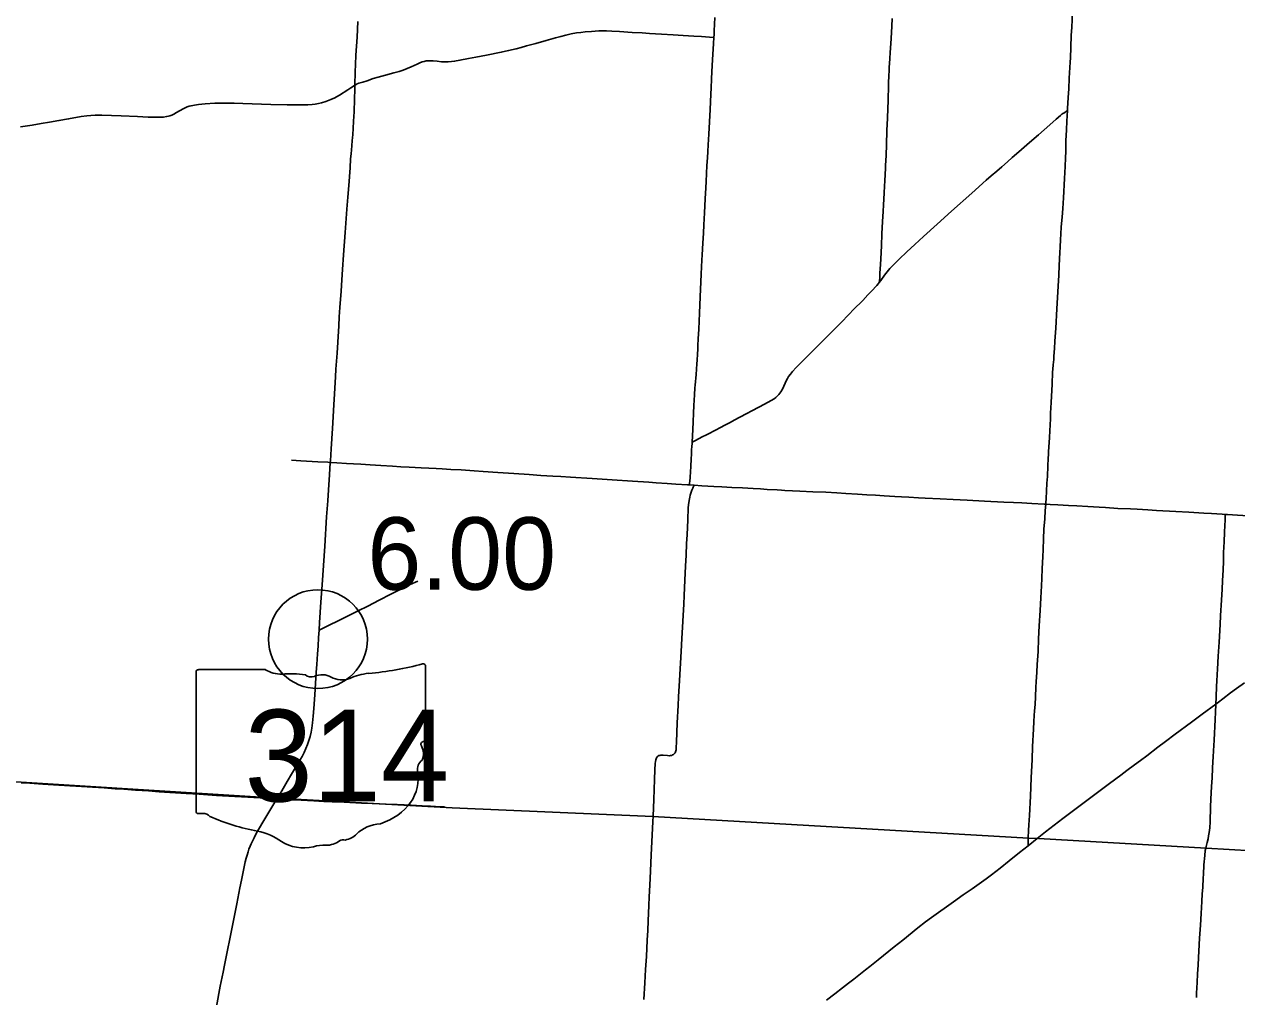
# Model space of a CAD drawing. Extents: x 1813937 to 1948437, y 826606 to 1022856.
# Drawn here: x 1908588 to 1926985, y 878544 to 893308 of the extents above; entities that cross this region are included whole.
import ezdxf

# ---------------------------------------------------------------- set-up
doc = ezdxf.new("R2010")
doc.units = 0
for name, color, linetype in [('Default', 7, 'Continuous'), ('GM_X_County_Road', 7, 'Continuous'), ('GM_X_State_Route', 7, 'Continuous'), ('GM_X_State_Shield', 7, 'Continuous'), ('GM_X_Township', 7, 'Continuous'), ('GM_X_Township_Road', 7, 'Continuous')]:
    doc.layers.add(name, color=color, linetype=linetype)

msp = doc.modelspace()

# ---------------------------------------------------------------- linework, layer by layer
at = {"layer": 'Default'}
msp.add_circle((1913044, 883973), 750, dxfattribs=at)
at = {"layer": 'GM_X_County_Road'}
for points in [[(1919051, 893107), (1919054, 893152), (1919057, 893206), (1919066, 893408)], [(1913604, 892383), (1913623, 892395), (1913639, 892402), (1913664, 892411), (1913727, 892430), (1913790, 892451), (1913881, 892483), (1913959, 892506), (1914070, 892537), (1914197, 892569), (1914276, 892590), (1914338, 892611), (1914400, 892635), (1914460, 892661), (1914548, 892704), (1914592, 892724), (1914623, 892735), (1914654, 892744), (1914685, 892750), (1914718, 892753), (1914750, 892753), (1914776, 892752), (1914791, 892751), (1914854, 892745), (1914920, 892738), (1914969, 892735), (1915019, 892736), (1915068, 892740), (1915117, 892747), (1915198, 892762), (1915326, 892787), (1915439, 892807), (1915600, 892836), (1915825, 892883), (1915937, 892907), (1916049, 892935), (1916128, 892956), (1916207, 892978), (1916349, 893018), (1916507, 893061), (1916648, 893102), (1916727, 893124), (1916806, 893144), (1916886, 893161), (1916966, 893175), (1917031, 893184), (1917096, 893191), (1917194, 893199), (1917308, 893206), (1917373, 893208), (1917422, 893207), (1917504, 893204), (1917618, 893196), (1917814, 893184), (1917962, 893176), (1918076, 893167), (1918256, 893157), (1918436, 893146), (1918583, 893137), (1918746, 893126), (1918861, 893120), (1918987, 893111), (1919051, 893107)], [(1913231, 886656), (1913331, 886648), (1913478, 886640), (1913585, 886634), (1913696, 886629), (1913835, 886620), (1913999, 886610), (1914177, 886598), (1914303, 886590), (1914428, 886584), (1914517, 886579), (1914609, 886574), (1914725, 886568), (1914839, 886562), (1914927, 886557), (1915059, 886551), (1915219, 886543), (1915415, 886527), (1915553, 886518), (1915772, 886503), (1916017, 886488), (1916247, 886473), (1916427, 886460), (1916607, 886449), (1916728, 886443), (1916876, 886433), (1917203, 886411), (1917507, 886391), (1917818, 886371), (1918064, 886355), (1918178, 886347), (1918342, 886336), (1918473, 886327), (1918653, 886315), (1918679, 886314)], [(1918679, 886314), (1918684, 886314), (1918751, 886310)], [(1918751, 886310), (1918868, 886303), (1919049, 886291), (1919170, 886285), (1919324, 886276), (1919486, 886268), (1919645, 886259), (1919758, 886253), (1919862, 886247), (1920014, 886238), (1920076, 886236), (1920128, 886231), (1920243, 886225), (1920357, 886220), (1920554, 886209), (1920751, 886202), (1920919, 886192), (1921054, 886185), (1921229, 886172), (1921372, 886165), (1921503, 886157), (1921634, 886148), (1921798, 886139), (1921896, 886132), (1922010, 886127), (1922158, 886119), (1922256, 886114), (1922485, 886102), (1922682, 886093), (1922895, 886083), (1923157, 886069), (1923449, 886055), (1923595, 886047), (1923723, 886041), (1923876, 886034), (1924062, 886022), (1924086, 886021)], [(1924086, 886021), (1924152, 886017), (1924272, 886010), (1924432, 886001), (1924559, 885995), (1924725, 885985), (1924898, 885976), (1924992, 885971), (1925178, 885959), (1925374, 885950), (1925473, 885944), (1925636, 885935), (1925767, 885928), (1926060, 885911), (1926257, 885899), (1926486, 885887), (1926601, 885879), (1926765, 885870), (1926812, 885867)], [(1926681, 883336), (1926686, 883438), (1926691, 883519), (1926703, 883715), (1926716, 883928), (1926732, 884197), (1926739, 884331), (1926751, 884567), (1926761, 884730), (1926769, 884861), (1926777, 885025), (1926781, 885151), (1926786, 885287), (1926792, 885451), (1926798, 885599), (1926802, 885697), (1926807, 885779), (1926811, 885855), (1926812, 885867)], [(1926812, 885867), (1926846, 885865), (1926994, 885854), (1927157, 885843)], [(1926666, 882988), (1926670, 883094), (1926678, 883258), (1926681, 883336)], [(1926666, 882988), (1926707, 883019), (1926773, 883068), (1926888, 883156), (1926983, 883225), (1927102, 883312)], [(1923954, 880947), (1923981, 880969), (1924084, 881050), (1924214, 881150), (1924345, 881249), (1924607, 881446), (1925053, 881780), (1925224, 881909), (1925316, 881977), (1925434, 882065), (1925526, 882133), (1925618, 882202), (1925787, 882332), (1925905, 882421), (1926050, 882529), (1926300, 882714), (1926458, 882832), (1926666, 882988)], [(1926627, 882187), (1926631, 882276), (1926636, 882358), (1926640, 882440), (1926655, 882751), (1926661, 882865), (1926666, 882979), (1926666, 882988)], [(1926515, 880801), (1926521, 880827), (1926536, 880888), (1926549, 880942), (1926558, 880985), (1926566, 881037), (1926574, 881110), (1926579, 881199), (1926588, 881429), (1926593, 881545), (1926603, 881736), (1926610, 881867), (1926618, 882015), (1926623, 882113), (1926627, 882187)], [(1908542, 881794), (1908673, 881785), (1908804, 881777), (1908869, 881773), (1909033, 881763), (1909278, 881747), (1909458, 881736), (1909624, 881726), (1909802, 881714), (1909966, 881703), (1910097, 881694), (1910277, 881682), (1910474, 881668), (1910637, 881657), (1911047, 881631), (1911243, 881618), (1911505, 881601), (1911783, 881585), (1911980, 881574), (1912259, 881558), (1912420, 881547)], [(1920758, 878492), (1920888, 878591), (1921005, 878681), (1921096, 878751), (1921174, 878812), (1921354, 878953), (1921418, 879004), (1921546, 879106), (1921789, 879301), (1921917, 879405), (1922147, 879589), (1922262, 879681), (1922354, 879750), (1922461, 879826), (1922581, 879911), (1922688, 879987), (1922836, 880090), (1922970, 880185), (1923077, 880260), (1923185, 880336), (1923264, 880395), (1923393, 880496), (1923533, 880609), (1923687, 880732), (1923818, 880838)], [(1923818, 880838), (1923954, 880947)], [(1926373, 878534), (1926376, 878599), (1926385, 878763), (1926391, 878894), (1926398, 879025), (1926405, 879140), (1926410, 879238), (1926421, 879434), (1926432, 879631), (1926444, 879810), (1926456, 879990), (1926462, 880105), (1926468, 880203), (1926475, 880351), (1926478, 880400), (1926486, 880547), (1926498, 880690), (1926507, 880763), (1926515, 880801)]]:
    msp.add_lwpolyline(points, dxfattribs=at)
at = {"layer": 'GM_X_State_Route'}
msp.add_lwpolyline([(1911506, 878396), (1911563, 878703), (1911604, 878919), (1911626, 879026), (1911752, 879649), (1911812, 879955), (1911861, 880196), (1911884, 880313), (1911926, 880517), (1911942, 880591), (1911954, 880646), (1911968, 880694), (1911983, 880745), (1911997, 880785), (1912014, 880829), (1912031, 880868), (1912045, 880898), (1912074, 880959), (1912108, 881023), (1912207, 881194), (1912420, 881547), (1912494, 881672), (1912578, 881813), (1912645, 881926), (1912755, 882109), (1912803, 882194), (1912833, 882252), (1912861, 882312), (1912886, 882372), (1912907, 882434), (1912926, 882496), (1912940, 882560), (1912952, 882624), (1912963, 882705), (1912973, 882803), (1912982, 882918), (1912995, 883130), (1913018, 883474), (1913026, 883589), (1913037, 883752), (1913045, 883867), (1913053, 883997), (1913061, 884110), (1913069, 884225), (1913090, 884536), (1913107, 884798), (1913128, 885093), (1913147, 885387), (1913176, 885829), (1913193, 886075), (1913204, 886238), (1913220, 886467), (1913231, 886656), (1913232, 886680), (1913243, 886860), (1913263, 887171), (1913285, 887531), (1913294, 887695), (1913310, 887957), (1913317, 888072), (1913334, 888316), (1913344, 888480), (1913359, 888732), (1913368, 888864), (1913377, 889008), (1913394, 889255), (1913406, 889426), (1913416, 889584), (1913433, 889805), (1913459, 890148), (1913483, 890499), (1913496, 890682), (1913511, 890862), (1913531, 891129), (1913540, 891267), (1913547, 891341), (1913556, 891464), (1913562, 891542), (1913566, 891586), (1913571, 891635), (1913578, 891725), (1913585, 891836), (1913592, 891977), (1913599, 892173), (1913603, 892321), (1913604, 892383), (1913608, 892583), (1913612, 892698), (1913618, 892841), (1913637, 893111), (1913651, 893349)], dxfattribs=at)
at = {"layer": 'GM_X_State_Shield'}
for p, q in [((1911195, 883474), (1911195, 881360)), ((1912249, 883510), (1911230, 883510)), ((1914676, 882457), (1914676, 883562)), ((1914676, 882457), (1914676, 882457))]:
    msp.add_line(p, q, dxfattribs=at)
for centre, major_axis, start_param, end_param in [((1913436, 886391), (3691, 0), 4.814394, 5.042369), ((1914637, 883567), (38.7, 0), 6.141152, 7.989035), ((1911235, 883478), (40.3, 0), 1.712693, 3.28349), ((1912492, 883755), (391, 0), 4.042523, 4.731795), ((1912621, 882324), (1404, 0), 1.404758, 1.657858), ((1912940, 883489), (113, 0), 3.836095, 5.185415), ((1913106, 883245), (235, 0), 0.950623, 2.079405), ((1913907, 882865), (743, 0), 1.699011, 2.107814), ((1913409, 883580), (282, 0), 4.081561, 5.145723), ((1914667, 882376), (60, 0), 1.883978, 3.671073), ((1914285, 882236), (360, 0), 5.934695, 6.695948), ((1914635, 882453), (41.5, 0), 5.05454, 6.418171), ((1914815, 881994), (262, 0), 2.387724, 3.262537), ((1913643, 881854), (923, 0), 5.101752, 6.440018), ((1911236, 881356), (40.7, 0), 3.00124, 4.508301), ((1911242, 881572), (310, 0), 4.665946, 4.897461), ((1911305, 881238), (112, 0), 0.519207, 1.627899), ((1912719, 883137), (2665, 0), 4.195997, 4.488961), ((1911924, 880411), (834, 0), 0.823519, 1.323587), ((1913392, 881156), (298, 0), 4.937069, 5.64225), ((1914032, 880767), (506, 0), 1.647645, 2.488434), ((1912826, 881228), (529, 0), 4.026481, 4.996735), ((1913132, 880497), (435, 0), 1.495662, 1.94098), ((1913170, 881070), (282, 0), 4.691044, 5.507374), ((1913425, 880865), (79.4, 0), 1.147584, 2.315152)]:
    msp.add_ellipse(centre, major_axis=major_axis, ratio=0.8, start_param=start_param, end_param=end_param, dxfattribs=at)
at = {"layer": 'GM_X_Township'}
msp.add_lwpolyline([(1929313, 880637), (1926519, 880798), (1923978, 880945), (1923826, 880954), (1918127, 881283), (1915079, 881414), (1912418, 881561), (1907482, 881867), (1902065, 882212), (1902276, 885593), (1902366, 887154), (1902378, 887248), (1902624, 890798), (1902935, 895772), (1903241, 901246), (1903453, 905734), (1903500, 906547), (1903661, 909327)], dxfattribs=at)
at = {"layer": 'GM_X_Township_Road'}
for points in [[(1921561, 889386), (1921563, 889414), (1921567, 889461), (1921570, 889527), (1921577, 889659), (1921582, 889747), (1921592, 889945), (1921601, 890125), (1921611, 890314), (1921618, 890465), (1921624, 890566), (1921634, 890742), (1921639, 890855), (1921643, 890926), (1921649, 891034), (1921653, 891117), (1921656, 891168), (1921659, 891235), (1921663, 891321), (1921668, 891477), (1921676, 891693), (1921684, 891883), (1921690, 892031), (1921695, 892145), (1921697, 892210), (1921700, 892324), (1921703, 892406), (1921707, 892535), (1921710, 892596), (1921710, 892612), (1921713, 892662), (1921716, 892709), (1921721, 892792), (1921727, 892873), (1921742, 893089), (1921752, 893279), (1921757, 893395)], [(1924416, 891996), (1924418, 892031), (1924427, 892195), (1924435, 892326), (1924444, 892489), (1924448, 892571), (1924457, 892734), (1924460, 892800), (1924466, 892954), (1924474, 893143), (1924480, 893258), (1924492, 893503)], [(1918723, 886964), (1918728, 887060), (1918733, 887157), (1918737, 887272), (1918742, 887403), (1918747, 887518), (1918757, 887681), (1918764, 887789), (1918767, 887830), (1918781, 887991), (1918793, 888155), (1918798, 888210), (1918805, 888301), (1918809, 888374), (1918810, 888433), (1918813, 888531), (1918821, 888678), (1918831, 888924), (1918842, 889169), (1918853, 889399), (1918860, 889513), (1918866, 889627), (1918871, 889726), (1918874, 889808), (1918884, 889987), (1918893, 890134), (1918899, 890265), (1918908, 890445), (1918919, 890658), (1918927, 890822), (1918932, 890920), (1918946, 891165), (1918953, 891279), (1918960, 891377), (1918966, 891476), (1918974, 891639), (1918995, 892016), (1919006, 892245), (1919011, 892343), (1919016, 892474), (1919021, 892589), (1919032, 892769), (1919046, 893014), (1919051, 893107)], [(1908532, 891749), (1908710, 891778), (1908846, 891802), (1908969, 891822), (1909114, 891845), (1909260, 891871), (1909454, 891906), (1909535, 891918), (1909600, 891923), (1909666, 891926), (1909764, 891927), (1909912, 891924), (1910059, 891918), (1910305, 891906), (1910469, 891898), (1910567, 891895), (1910649, 891896), (1910699, 891899), (1910747, 891906), (1910779, 891913), (1910795, 891917), (1910826, 891929), (1910855, 891943), (1910899, 891966), (1910998, 892024), (1911027, 892039), (1911058, 892052), (1911089, 892062), (1911120, 892070), (1911169, 892079), (1911234, 892088), (1911332, 892098), (1911479, 892109), (1911561, 892112), (1911627, 892112), (1911774, 892108), (1911905, 892103), (1912331, 892090), (1912578, 892085), (1912692, 892083), (1912807, 892083), (1912889, 892085), (1912955, 892089), (1913003, 892095), (1913052, 892103), (1913099, 892116), (1913162, 892137), (1913238, 892166), (1913299, 892191), (1913328, 892206), (1913370, 892231), (1913495, 892310), (1913544, 892342), (1913582, 892368), (1913604, 892383)], [(1921561, 889386), (1921584, 889418), (1921641, 889498), (1921681, 889550), (1921723, 889600), (1921768, 889647), (1921862, 889740), (1921980, 889852), (1922099, 889965), (1922232, 890086), (1922439, 890272), (1922659, 890469), (1922964, 890743), (1923184, 890940), (1923258, 891005), (1923345, 891080), (1923419, 891145), (1923504, 891221), (1923578, 891286), (1923677, 891372), (1923839, 891511), (1923975, 891629), (1924148, 891780), (1924246, 891867), (1924308, 891921), (1924333, 891942), (1924346, 891952), (1924360, 891960), (1924416, 891996)], [(1924086, 886021), (1924088, 886044), (1924093, 886107), (1924098, 886221), (1924105, 886340), (1924111, 886440), (1924117, 886604), (1924123, 886715), (1924127, 886783), (1924129, 886815), (1924134, 886895), (1924142, 887031), (1924147, 887141), (1924152, 887223), (1924158, 887322), (1924161, 887403), (1924168, 887566), (1924183, 887845), (1924191, 888025), (1924195, 888074), (1924200, 888139), (1924207, 888220), (1924211, 888269), (1924219, 888383), (1924226, 888498), (1924238, 888695), (1924254, 888989), (1924274, 889333), (1924284, 889497), (1924292, 889644), (1924301, 889841), (1924305, 889923), (1924310, 890038), (1924314, 890119), (1924323, 890233), (1924334, 890379), (1924344, 890510), (1924350, 890591), (1924356, 890673), (1924361, 890771), (1924365, 890870), (1924370, 890968), (1924380, 891147), (1924386, 891278), (1924390, 891376), (1924392, 891475), (1924392, 891540), (1924399, 891704), (1924406, 891835), (1924416, 891996)], [(1918723, 886964), (1918774, 886989), (1918875, 887042), (1918938, 887073), (1918992, 887102), (1919044, 887129), (1919087, 887152), (1919144, 887183), (1919230, 887227), (1919298, 887264), (1919357, 887296), (1919821, 887540), (1919922, 887595), (1919964, 887620), (1919990, 887640), (1920014, 887662), (1920036, 887687), (1920065, 887726), (1920091, 887768), (1920113, 887812), (1920133, 887857), (1920145, 887887), (1920169, 887930), (1920186, 887958), (1920215, 887998), (1920246, 888036), (1920302, 888097), (1920403, 888200), (1920491, 888288), (1920595, 888393), (1920687, 888486), (1920791, 888590), (1920884, 888683), (1920976, 888776), (1921102, 888905), (1921171, 888975), (1921309, 889115), (1921388, 889198), (1921445, 889257), (1921524, 889340), (1921545, 889365), (1921561, 889386)], [(1918679, 886314), (1918683, 886344), (1918686, 886365), (1918693, 886430), (1918699, 886512), (1918703, 886595), (1918707, 886709), (1918711, 886779), (1918714, 886842), (1918719, 886902), (1918721, 886940), (1918723, 886964)], [(1912641, 886691), (1912785, 886682), (1913044, 886665), (1913195, 886658), (1913231, 886656)], [(1918129, 881284), (1918138, 881538), (1918150, 881845), (1918157, 881990), (1918163, 882083), (1918166, 882116), (1918170, 882141), (1918175, 882157), (1918181, 882172), (1918189, 882186), (1918201, 882198), (1918215, 882205), (1918231, 882209), (1918247, 882211), (1918264, 882212), (1918280, 882211), (1918346, 882206), (1918379, 882204), (1918395, 882205), (1918411, 882209), (1918426, 882215), (1918440, 882223), (1918452, 882235), (1918462, 882248), (1918469, 882262), (1918474, 882278), (1918478, 882294), (1918481, 882327), (1918484, 882409), (1918495, 882704), (1918508, 882966), (1918516, 883097), (1918531, 883343), (1918557, 883785), (1918566, 883982), (1918593, 884506), (1918599, 884638), (1918611, 884867), (1918622, 885080), (1918630, 885247), (1918638, 885424), (1918644, 885555), (1918654, 885785), (1918662, 885965), (1918666, 886013), (1918675, 886078), (1918684, 886127), (1918691, 886158), (1918701, 886190), (1918719, 886235), (1918732, 886265), (1918738, 886279), (1918751, 886310)], [(1923820, 880956), (1923824, 881070), (1923829, 881152), (1923839, 881298), (1923853, 881591), (1923866, 881870), (1923878, 882148), (1923888, 882345), (1923900, 882607), (1923908, 882722), (1923913, 882813), (1923918, 882885), (1923924, 882983), (1923931, 883098), (1923937, 883245), (1923941, 883326), (1923949, 883474), (1923956, 883588), (1923964, 883719), (1923969, 883784), (1923979, 883980), (1923989, 884177), (1924003, 884406), (1924006, 884503), (1924011, 884602), (1924021, 884782), (1924026, 884896), (1924033, 885044), (1924043, 885223), (1924048, 885335), (1924050, 885494), (1924060, 885642), (1924071, 885802), (1924078, 885928), (1924086, 886021)], [(1913061, 884110), (1913174, 884164), (1913389, 884270), (1913653, 884402), (1913800, 884476), (1913975, 884566), (1914151, 884656), (1914312, 884738), (1914444, 884801), (1914559, 884855)], [(1912420, 881547), (1912541, 881539), (1912639, 881533), (1912787, 881527), (1912983, 881518), (1913131, 881511), (1913262, 881505), (1913442, 881496), (1913704, 881485), (1913868, 881477), (1914081, 881468), (1914245, 881462), (1914458, 881452), (1914625, 881444), (1914753, 881438), (1914901, 881429), (1914963, 881427)], [(1917988, 878501), (1918002, 878754), (1918015, 878960), (1918028, 879157), (1918040, 879403), (1918047, 879551), (1918055, 879698), (1918064, 879928), (1918070, 880059), (1918079, 880240), (1918089, 880453), (1918101, 880699), (1918110, 880896), (1918126, 881207), (1918129, 881284)], [(1923818, 880838), (1923819, 880884), (1923819, 880941), (1923820, 880956)]]:
    msp.add_lwpolyline(points, dxfattribs=at)

# ---------------------------------------------------------------- texts
at = {"layer": 'Default'}
msp.add_text('6.00', height=1100, dxfattribs=at).set_placement((1913794, 884723))
at = {"layer": 'GM_X_State_Shield'}
msp.add_text('314', height=1392.2, dxfattribs=at).set_placement((1911929, 881509))

doc.saveas('drawing.dxf')
